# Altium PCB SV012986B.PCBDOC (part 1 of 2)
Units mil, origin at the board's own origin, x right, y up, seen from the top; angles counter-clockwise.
Board outline 2107 x 1920 mil, 4 copper layers (Top Layer, Mid-Layer 1, Mid-Layer 2, Bottom Layer), stack 59.6 mil thick; 51 components, 50 nets, 187 pads, 58 vias.
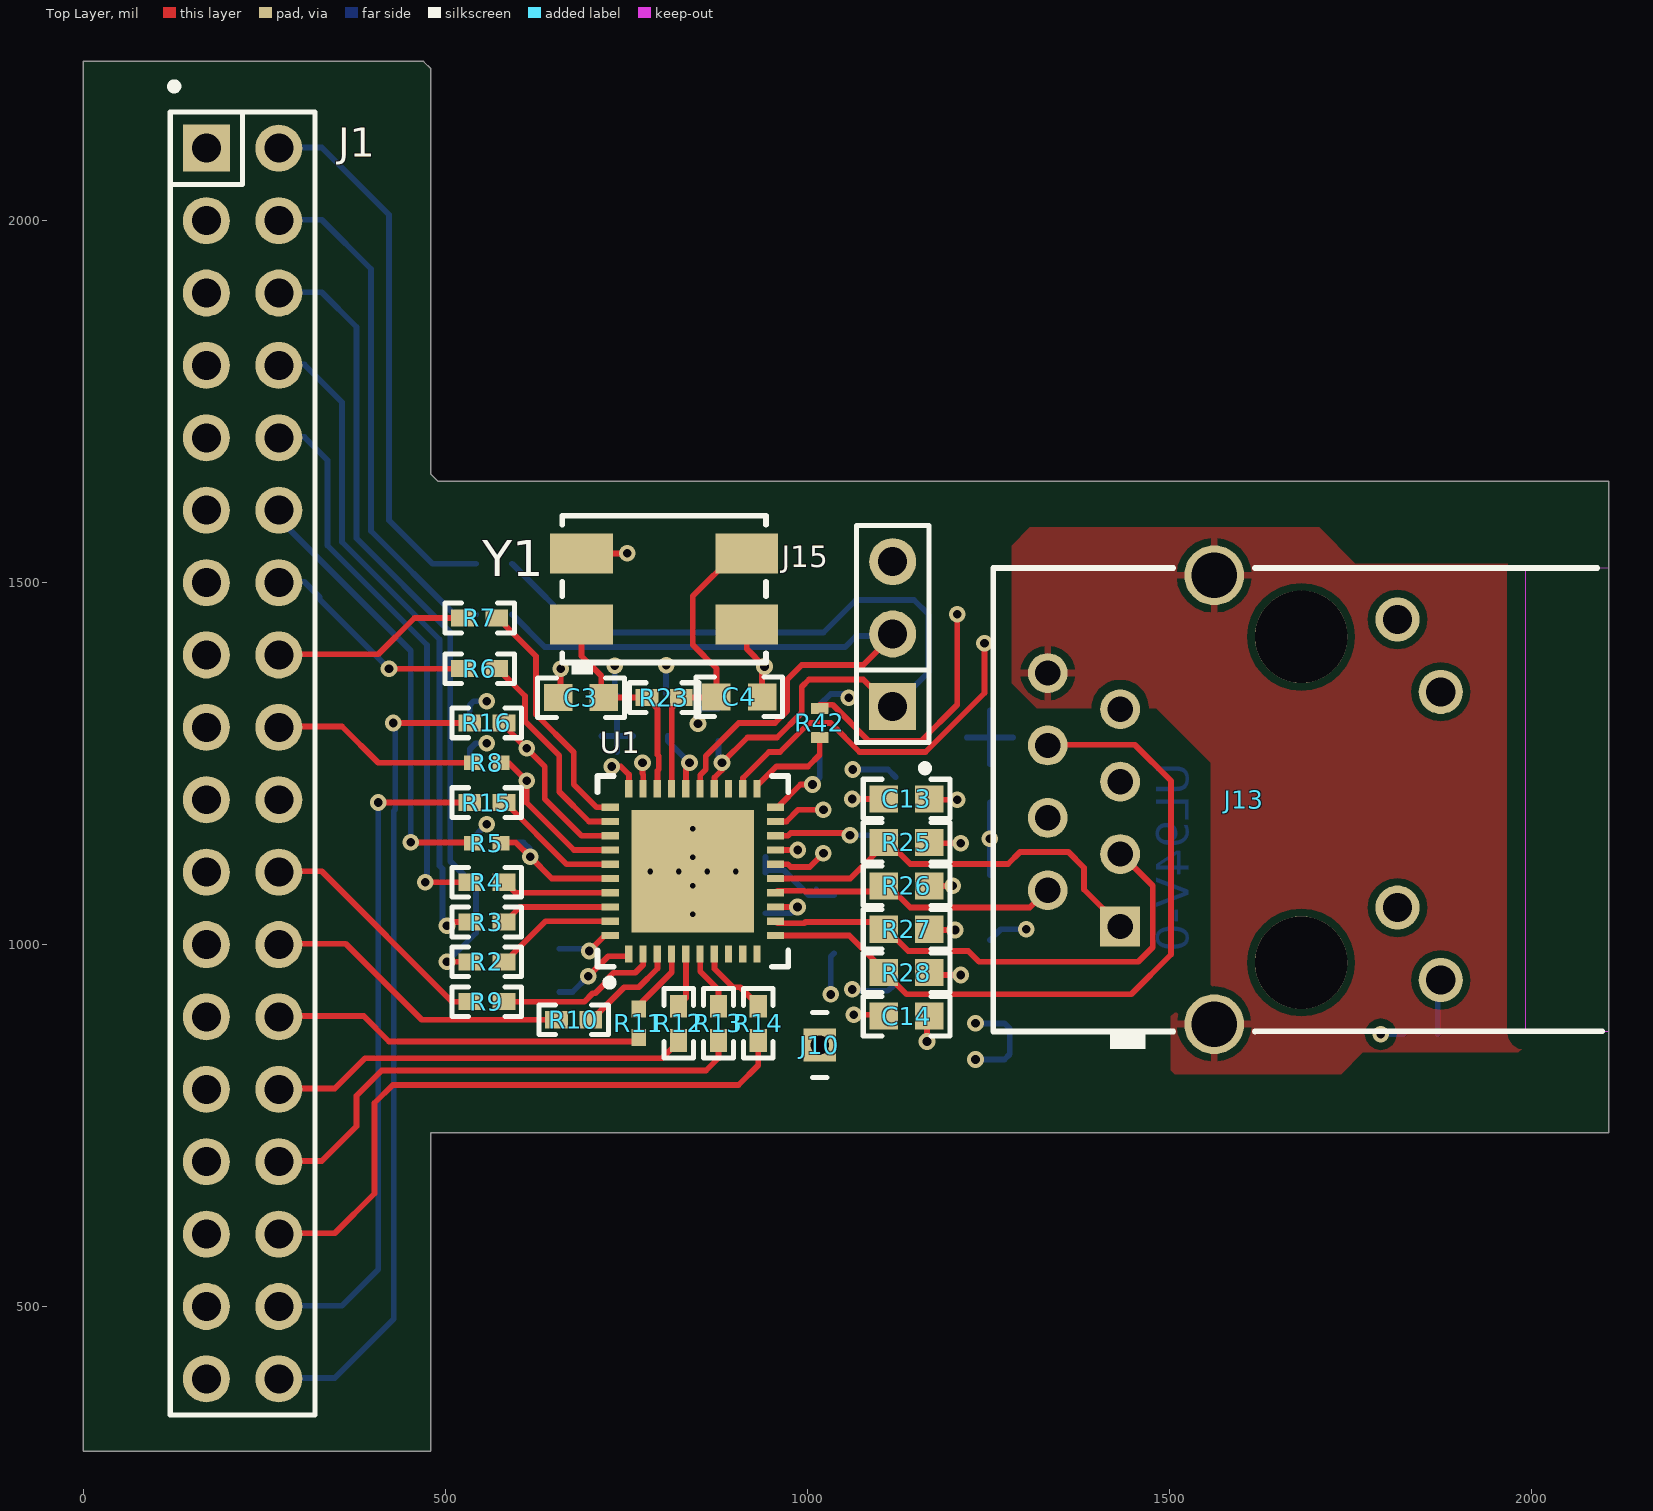
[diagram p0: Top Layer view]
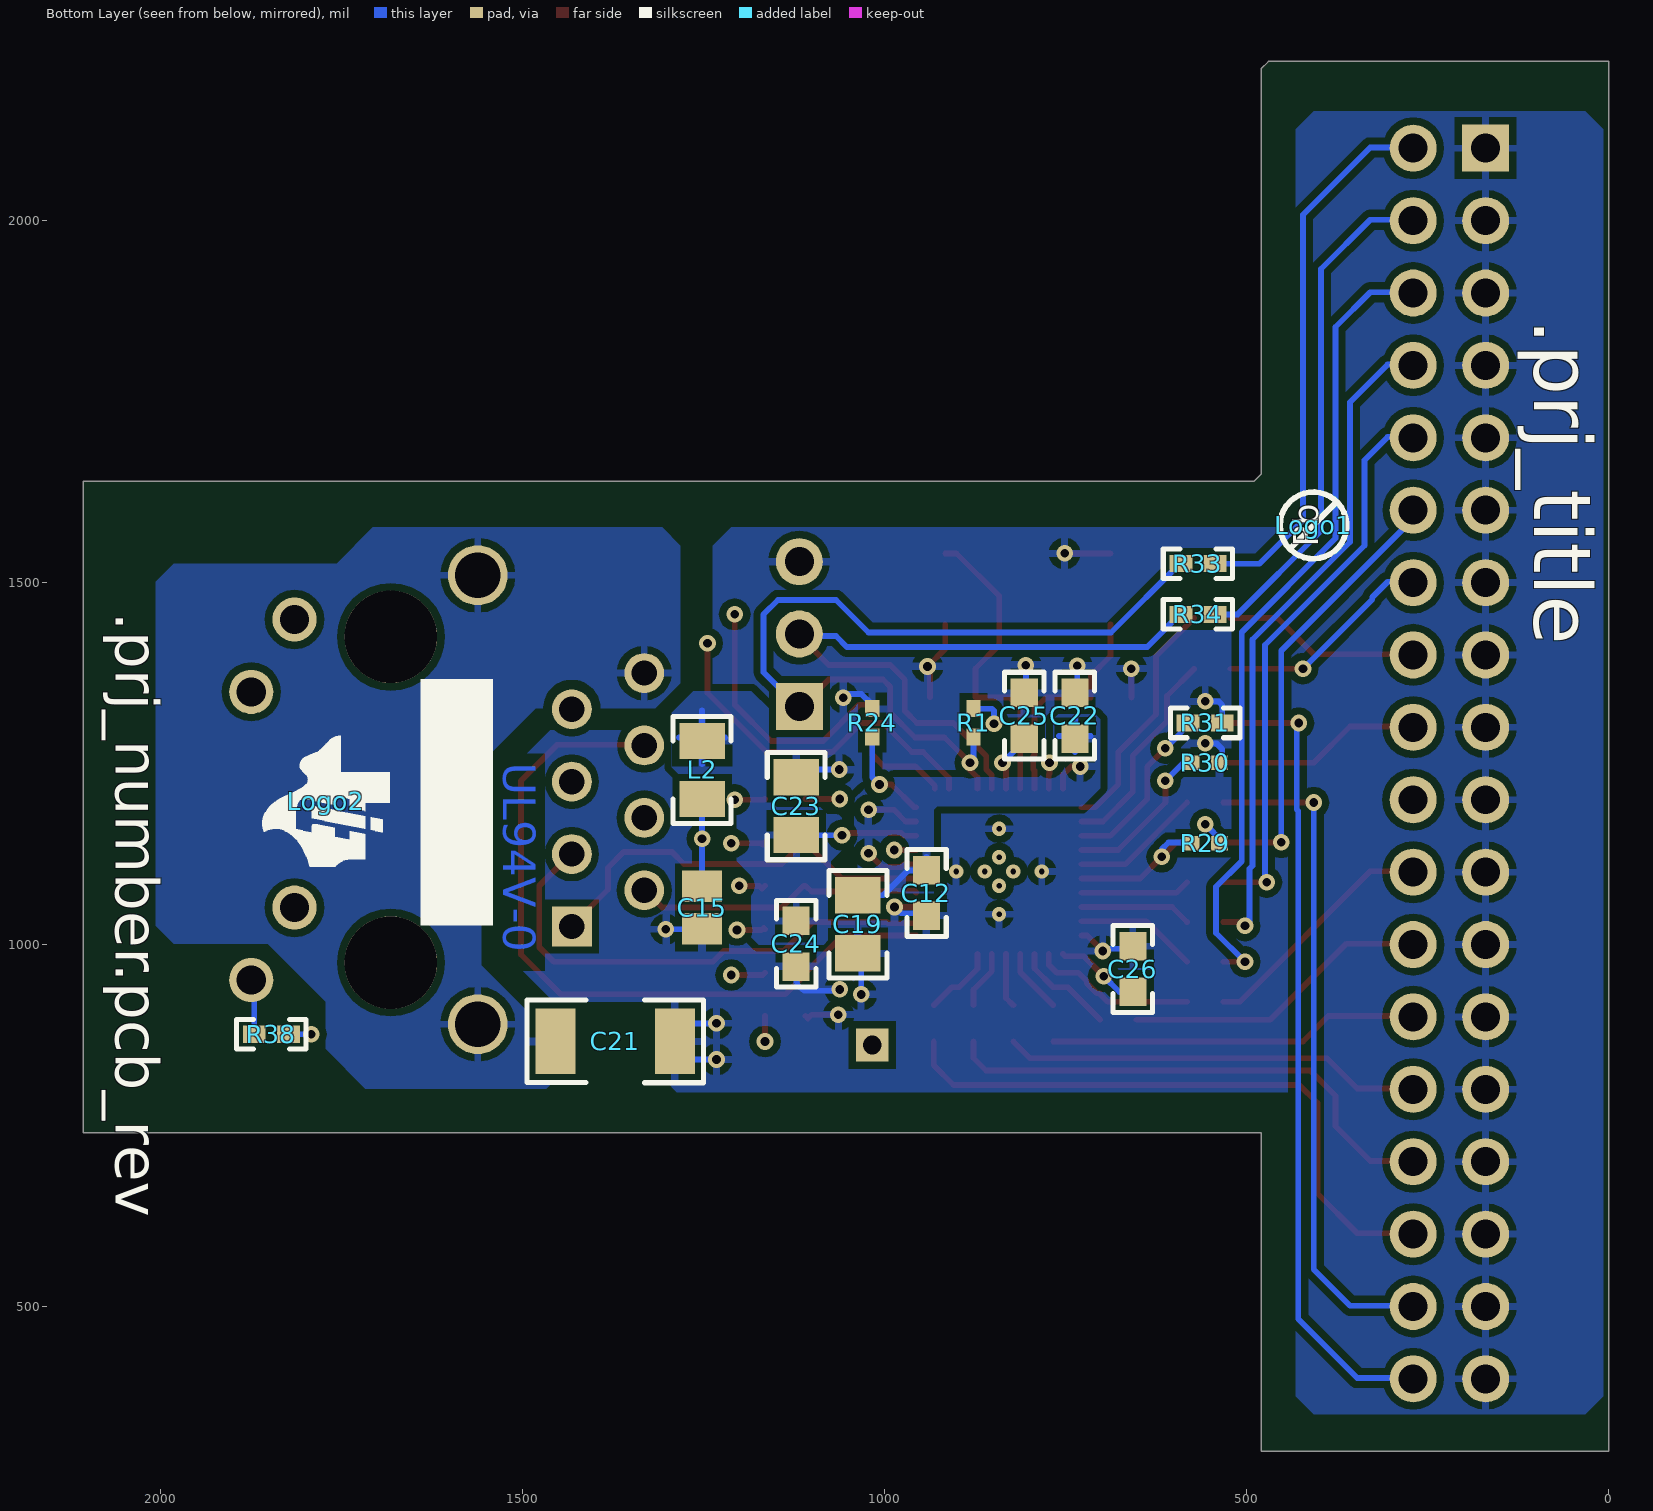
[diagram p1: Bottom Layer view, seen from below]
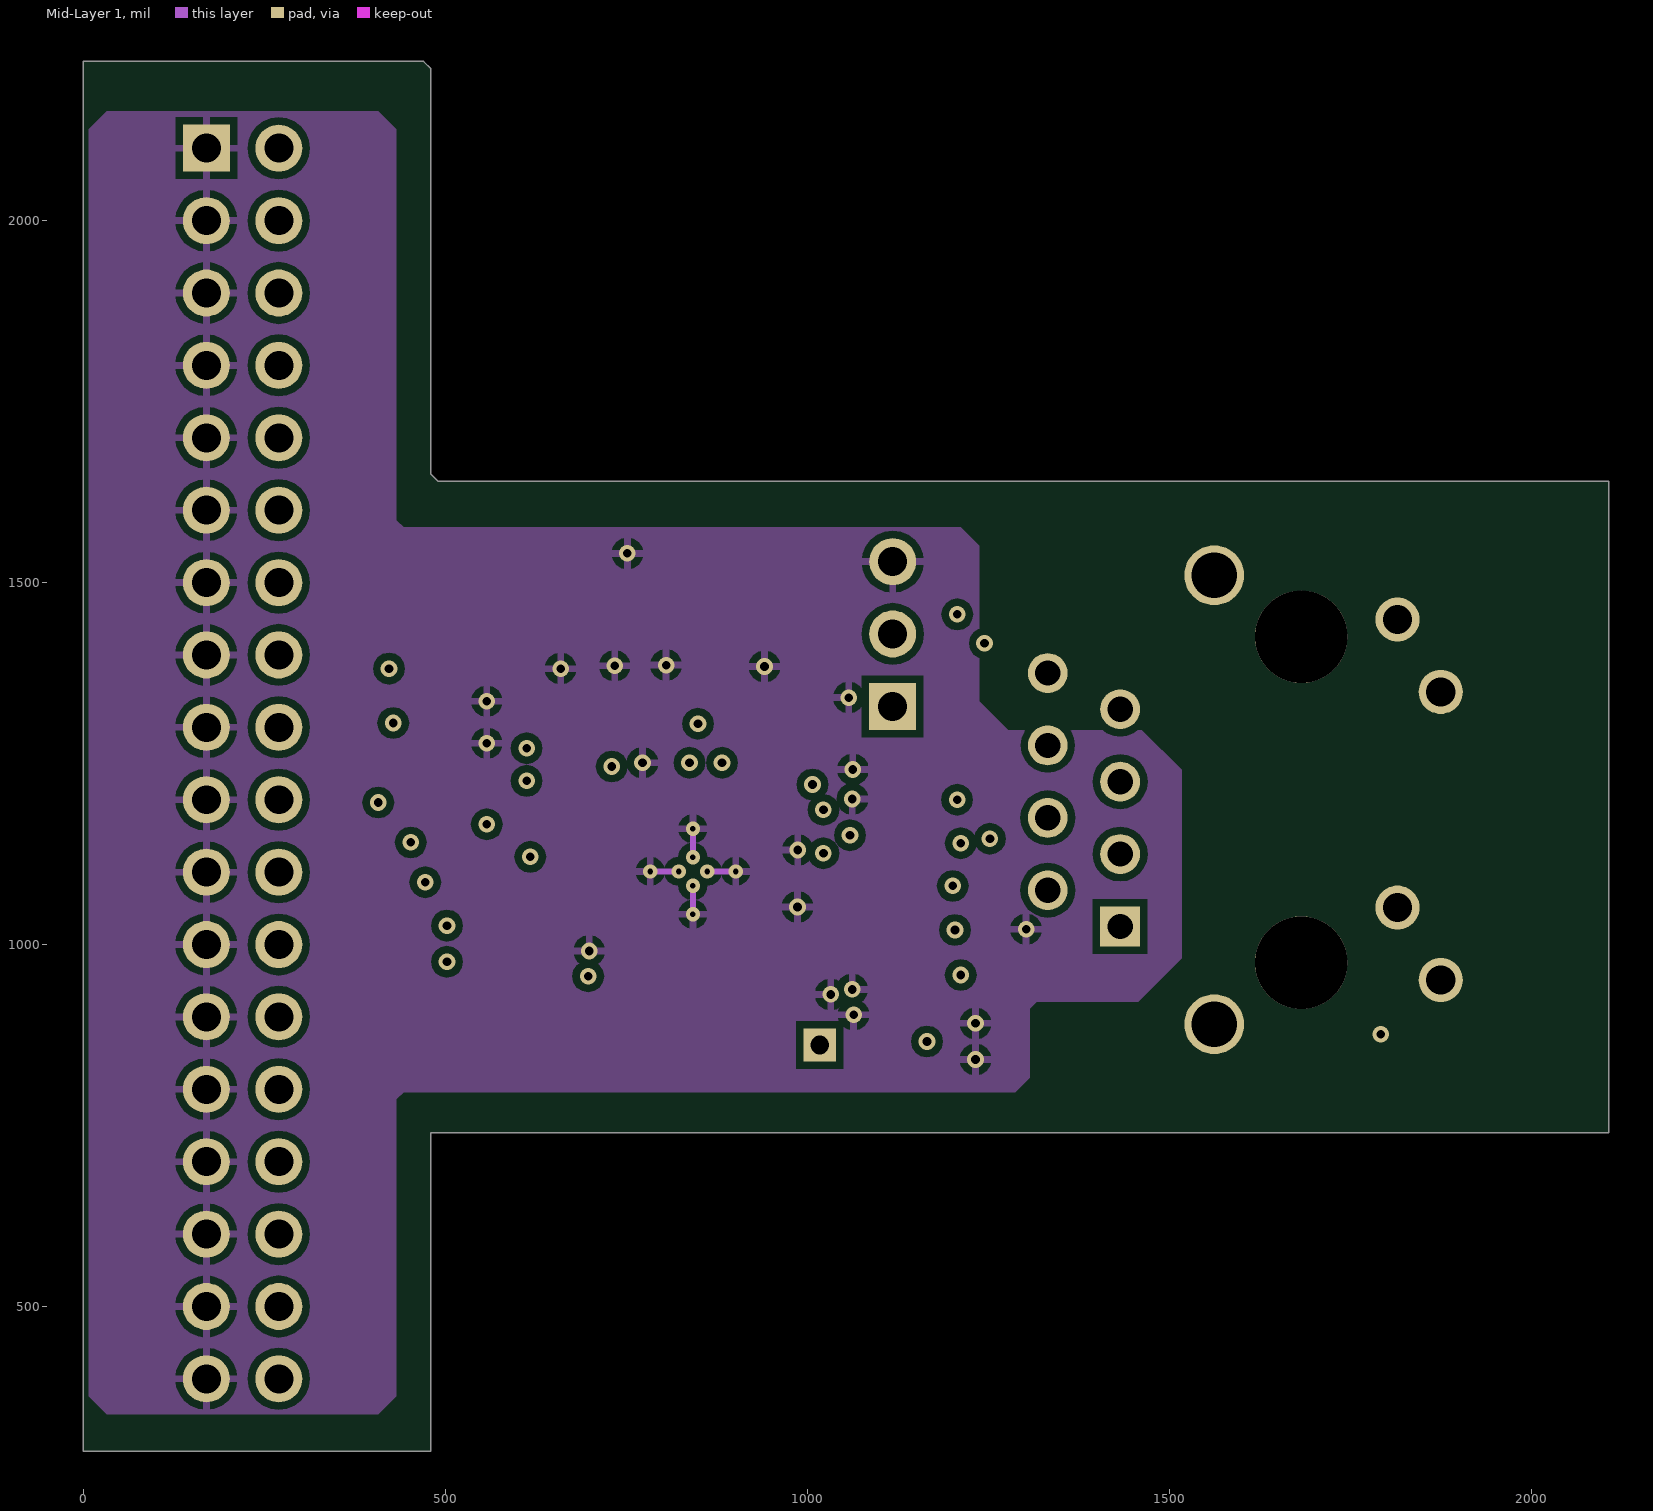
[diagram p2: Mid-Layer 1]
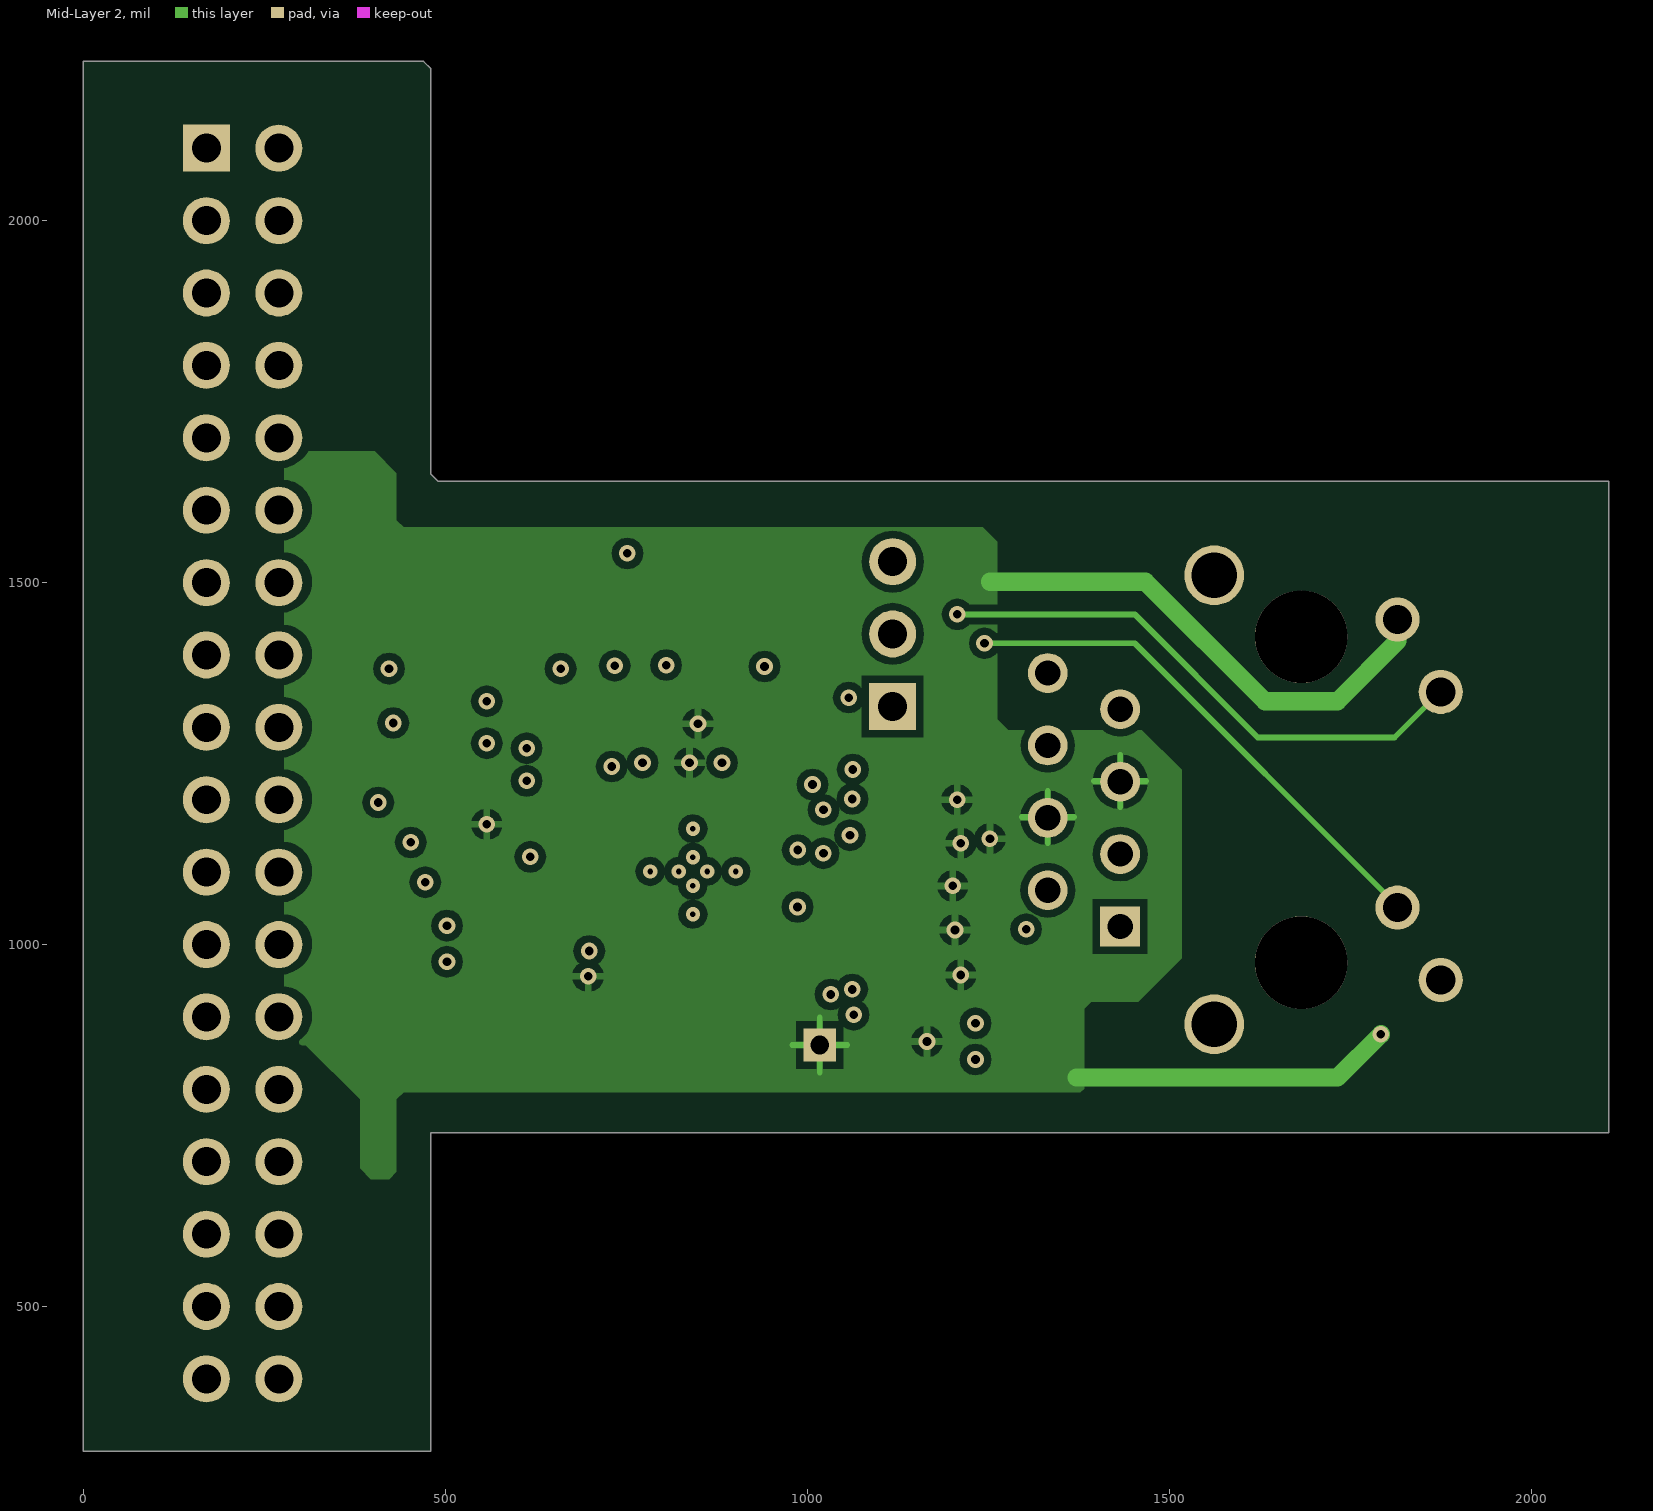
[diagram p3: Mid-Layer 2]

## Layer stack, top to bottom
Top Solder: solder mask 0.4, Solder Resist, Dk 3.5
Top Layer: signal copper 1.4
Dielectric1: core 4, FR-4, Dk 4.8
Mid-Layer 1: signal copper 1.4
Dielectric3: dielectric 46, FR-4, Dk 4.8
Mid-Layer 2: signal copper 1.4
Dielectric2: dielectric 4, FR-4, Dk 4.8
Bottom Layer: signal copper 1.4
Bottom Solder: solder mask 0.4, Solder Resist, Dk 3.5

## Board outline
0,300 0,2220 470,2220 480,2210 480,1650 490,1640 2107,1640 2107,740 480,740 480,300

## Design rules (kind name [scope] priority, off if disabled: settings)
AcuteAngle [All] p1: minimum=4.50000000000000E+0001 checktracksonly=FALSE
AssemblyTestPointUsage [All] p1: valid=2
Clearance Clearance_Keepouts [((IsTrack Or IsArc) And Not InPoly) And IsFree and IsKeepOut vs ((IsTrack Or IsArc) And Not InPoly) And IsFree and IsKeepOut] p1: gap=0
Clearance Clearance_BoardEdge_MountingHoles [OnCopper and InComponentClass('Mounting Holes') vs IsKeepOut] p2: gap=40
Clearance Clearance_BoardEdge_Poly [OnCopper and InPoly vs IsKeepOut] p3: gap=25
Clearance Clearance_BoardEdge [OnCopper and Not InComponentClass('Logo') and not InComponentClass('FiducialMark') and not InRegion(1000,500,4000,800) and Not IsKeepout vs IsKeepOut] p4: gap=75
Clearance Clearance_Poly [InPolygon] p5: gap=10
Clearance [All] p6: gap=6
ComponentClearance ComponentClearance_MountingHoles_FiducialMarks [InComponentClass('Mounting Holes') vs InComponentClass('FiducialMark')] p1: gap=50 collisioncheckmode=3 verticalgap=10 showdistances=FALSE
ComponentClearance ComponentClearance_Shunt [InComponentClass('Header') vs InComponentClass('Shunt')] p2: gap=0 collisioncheckmode=3 verticalgap=0 showdistances=FALSE
ComponentClearance ComponentClearance_Logo [InComponentClass('Logo')] p3: gap=44 collisioncheckmode=3 verticalgap=10 showdistances=FALSE
ComponentClearance ComponentClearance_ScrewToNut [(HasFootprint('NY PMS 440 0025 PH')) vs (HasFootprint('Keystone_1902C'))] p4: gap=5 collisioncheckmode=3 verticalgap=10 showdistances=FALSE
ComponentClearance ComponentClearance_MountingHoles [InComponentClass('Mounting Holes')] p5: gap=250 collisioncheckmode=3 verticalgap=100000 showdistances=FALSE
ComponentClearance ComponentClearance_SmallPassives [HasFootprint('0201*') or HasFootprint('0402*') or HasFootprint('0508') or HasFootprint('0603*') or HasFootprint('0612') or HasFootprint('0805*') or HasFootprint('0815*') or HasFootprint('0830*') or HasFootprint('1206*') or HasFootprint('1210*') or HasFootprint('1808*') or HasFootprint('1812*') or HasFootprint('1825*') or HasFootprint('2010*') or HasFootprint('2220*') or HasFootprint('2225*') or HasFootprint('2512*') or HasFootprint('2728*') or HasFootprint('3518*') vs HasFootprint('0201*') or HasFootprint('0402*') or HasFootprint('0508') or HasFootprint('0603*') or HasFootprint('0612') or HasFootprint('0805*') or HasFootprint('0815*') or HasFootprint('0830*') or HasFootprint('1206*') or HasFootprint('1210*') or HasFootprint('1808*') or HasFootprint('1812*') or HasFootprint('1825*') or HasFootprint('2010*') or HasFootprint('2220*') or HasFootprint('2225*') or HasFootprint('2512*') or HasFootprint('2728*') or HasFootprint('3518*')] p6: gap=20 collisioncheckmode=3 verticalgap=10 showdistances=FALSE
ComponentClearance ComponentClearance_THtoSMT [IsThruComponent vs IsSMTComponent] p7: gap=28 collisioncheckmode=3 verticalgap=30 showdistances=FALSE
ComponentClearance ComponentClearance_THtoTH [IsThruComponent vs IsThruComponent] p8: gap=80 collisioncheckmode=3 verticalgap=30 showdistances=FALSE
ComponentClearance [All] p9: gap=29 collisioncheckmode=3 verticalgap=40 showdistances=FALSE
DiffPairsRouting [All] p1: maxlimit=100 minlimit=10 mostfreqgap=10 toplayer_minwidth=15 toplayer_maxwidth=15 toplayer_prefwidth=15 midlayer1_minwidth=15 midlayer1_maxwidth=15 midlayer1_prefwidth=15 midlayer2_minwidth=15 midlayer2_maxwidth=15 midlayer2_prefwidth=15 bottomlayer_minwidth=15 bottomlayer_maxwidth=15 bottomlayer_prefwidth=15 maxuncoupledlength=1000
FabricationTestPointUsage TestPointUsage [All] p1: valid=2 allowmultiple=FALSE
FabricationTestpoint Testpoint [All] p1: side=3 testpointundercomponent=TRUE minsize=40 maxsize=100 preferedsize=60 minholesize=0 maxholesize=40 preferedholesize=32 testpointgrid=1 allowsidetop=TRUE allowsidebottom=TRUE usegrid=TRUE gridtolerance=0.01
FanoutControl Fanout_LCC [IsLCC] p1: bgadir=Out bgaviamode=Centered fanoutstyle=Auto fanoutdirection=Alternating viagrid=1 // Fanout_LCC (Default Rule)
FanoutControl Fanout_BGA [IsBGA] p2: bgadir=Out bgaviamode=Centered fanoutstyle=Auto fanoutdirection=Alternating viagrid=1 // Fanout_BGA (Default Rule)
FanoutControl Fanout_Default [All] p4: bgadir=Out bgaviamode=Centered fanoutstyle=Auto fanoutdirection=Alternating viagrid=1 // Fanout_Default (Default Rule)
FanoutControl Fanout_Small [(CompPinCount < 5)] p5: bgadir=Out bgaviamode=Centered fanoutstyle=Auto fanoutdirection=OutThenIn viagrid=1 // Fanout_Small (Default Rule)
HoleSize [All] p1: absolutevalues=TRUE maxlimit=251 minlimit=7 maxpercent=80.000 minpercent=20.000
MinimumAnnularRing MinimumAnnularRing_ThermalPadVias [IsVia and InAnyComponent] p1: minimumring=5.91
MinimumAnnularRing [All] p2: minimumring=5
MinimumSolderMaskSliver MinimumSolderMaskSliver_Logo [InComponentClass('Logo') vs InComponentClass('Logo')] p1: minsoldermaskwidth=0.7
MinimumSolderMaskSliver [All] p2: minsoldermaskwidth=0.08
PlaneConnect [All] p1: planeconnectstyle=Relief reliefexpansion=10 reliefentries=4 reliefconductorwidth=10 reliefairgap=10
PolygonConnect [All] p1: connectstyle=Relief reliefconductorwidth=10 reliefentries=4 polygonreliefangle="90 Angle" airgapwidth=10
RoutingVias ThermalPadVias [IsVia and InAnyComponent] p1: holewidth=7.87 width=19.68 viastyle="Through Hole" minholewidth=7.87 minwidth=19.68 maxholewidth=12.99 maxwidth=23.62
RoutingVias [All] p2: holewidth=16 width=34 viastyle="Through Hole" minholewidth=7.87 minwidth=20 maxholewidth=40 maxwidth=65
SilkToBoardRegionClearance [Not ((IsComment or IsDesignator) And (Hide <> 'False')) and not InRegion(1000,500,4000,800)] p1:
SilkToSilkClearance SilkToSilkClearance_Pb-FreeLogo [(HasFootprint('Pb-Free_Overlay_Medium') OR HasFootprint('Pb-Free_Overlay_Small')) vs (HasFootprint('Pb-Free_Overlay_Medium') OR HasFootprint('Pb-Free_Overlay_Small'))] p1: silktosilkclearance=0
SilkToSilkClearance [All] p2: silktosilkclearance=5
SilkToSolderMaskClearance "Silk to Solder Mask Opening" [All] p1: minsilkscreentomaskgap=0 clearancetoexposedcopper=FALSE
SolderMaskExpansion [All] p1: expansion=1.97
UnpouredPolygon [All] p1: allowunpoured=FALSE
Width [All] p1: maxlimit=100 minlimit=6 preferedwidth=10 checkconnectedcopper=TRUE
14 further rules are at their usual default settings.

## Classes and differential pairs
component class Header: J1 J15
component class Logo: Logo2

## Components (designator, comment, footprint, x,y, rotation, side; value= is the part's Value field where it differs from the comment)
C3 "GRM1885C1H180JA01D" 0603 687.3,1341.1 r180 top
C4 "GRM1885C1H180JA01D" 0603 906,1342 r0 top
C12 "GRM188R61C104KA01D" 0603 942.3,1071.1 r270 bottom
C13 "GRM188R61C104KA01D" 0603 1137.3,1201.1 r180 top
C14 "GRM188R61C104KA01D" 0603 1137.3,901.1 r180 top
C15 "C0805C106M8PACTU" 0805L 1252.3,1051.1 r90 bottom
C19 "C0805C106M8PACTU" 0805_HV 1037,1028 r90 bottom
C21 "GR442QR73D152KW01L" 1808 1372.3,866.1 r180 bottom
C22 "GRM188R61C104KA01D" 0603 737.3,1316.1 r90 bottom
C23 "GRM216R61A105KA01D" 0805_HV 1122.3,1191.1 r270 bottom
C24 "GRM188R61C104KA01D" 0603 1122.3,1001.1 r90 bottom
C25 "GRM188R61C104KA01D" 0603 807.3,1316.1 r90 bottom
C26 "GRM188R61C104KA01D" 0603 657.3,966.1 r270 bottom
J1 "TSW-118-07-G-D" TSW-118-07-G-D 220,1250 r270 top
J10 "TMS-101-02-T-S" SAMTEC_TMS-101-02-T-S 1017.3,861.1 r0 top
J13 "J0011D21BNL" Pulse_J0011D21BNL 2107,1200 r90 top
J15 "TSW-103-07-G-S" TSW-103-07-G-S 1118,1429 r90 top
L2 "BLM21AG121SN1D" 0805_HV 1252.3,1241.1 r270 bottom
Logo1 "Pb-Free Symbol" Pb-Free_Overlay_Small 408,1579 r90 bottom
Logo2 "Texas Instruments" TI_Symbol_Overlay_Small 1772,1198 r270 bottom
R1 "CRCW04021K50FKED" 0402L 877.3,1306.1 r90 bottom
R2 "CRCW040247R0JNED" 0402 557.3,976.1 r0 top
R3 "CRCW040247R0JNED" 0402 557.3,1031.1 r0 top
R4 "CRCW040247R0JNED" 0402 557.3,1086.1 r0 top
R5 "CRCW040247R0JNED" 0402L 557,1140 r0 top
R6 "CRCW040247R0JNED" 0402 547.3,1381.1 r0 top
R7 "CRCW040247R0JNED" 0402 547.3,1451.1 r0 top
R8 "CRCW040247R0JNED" 0402L 557.3,1251.1 r0 top
R9 "CRCW040247R0JNED" 0402 557.3,921.1 r0 top
R10 "CRCW040233R0JNED" 0402 677.3,896.1 r0 top
R11 "CRCW040233R0JNED" 0402L 767.3,891.1 r90 top
R12 "CRCW040233R0JNED" 0402 822.3,891.1 r90 top
R13 "CRCW040233R0JNED" 0402 877.3,891.1 r90 top
R14 "CRCW040233R0JNED" 0402 932.3,891.1 r90 top
R15 "CRCW040247R0JNED" 0402 557.3,1196.1 r0 top
R16 "CRCW040247R0JNED" 0402 557.3,1306.1 r0 top
R23 "CRCW04021M00JNED" 0402 802.3,1341.1 r180 top
R24 "CRCW04024K87FKED" 0402L 1017.3,1306.1 r90 bottom
R25 "CRCW060349R9FKEA" 0603 1137.3,1141.1 r0 top
R26 "CRCW060349R9FKEA" 0603 1137.3,1081.1 r0 top
R27 "CRCW060349R9FKEA" 0603 1137.3,1021.1 r0 top
R28 "CRCW060349R9FKEA" 0603 1137.3,961.1 r0 top
R29 "CRCW04022K20JNED" 0402L 557,1140 r180 bottom
R30 "CRCW04022K20JNED" 0402L 557.3,1251.1 r0 bottom
R31 "CRCW04022K20JNED" 0402 557.3,1306.1 r180 bottom
R33 "CRCW04020000Z0ED" 0402 567.3,1526.1 r0 bottom
R34 "CRCW04020000Z0ED" 0402 567.3,1456.1 r0 bottom
R38 "CRCW0402274RFKED" 0402 1847.3,876.1 r180 bottom
R42 "CRCW0402274RFKED" 0402S 1017.3,1306.1 r90 top
U1 "DP83848J/K" SQA40B 842,1101 r90 top
Y1 "EA5070PA18-25.000M" Ecliptek_EA5070 802.3,1491.1 r90 top

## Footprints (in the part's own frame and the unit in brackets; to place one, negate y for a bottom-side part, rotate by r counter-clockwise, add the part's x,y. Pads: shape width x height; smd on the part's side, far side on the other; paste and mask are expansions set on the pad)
0402 [mm] "0402 from SM-752 data"
  rect 0.8x0.6 smd: 1(-0.6,0) 2(0.6,0)
  silkscreen extent -1.22,-0.52 1.22,0.52, body extent -0.55,-0.3 0.55,0.3, height 0.6
0402L [mm] "0402 from SM-752 data"
  rect 0.6x0.5 smd: 1(-0.5,0) 2(0.5,0)
  body extent -0.55,-0.3 0.55,0.3, height 0.6
0402S [mil] "Based on C0402S footprint from PADS legacy"
  rect 15x24 smd: 1(-20,0) 2(20,0)
  body extent -22,-12 22,12, height 24
0603 [mm] "0603 from SM-752 data"
  rect 1x0.95 smd: 1(-0.8,0) 2(0.8,0)
  silkscreen extent -1.52,-0.69 1.52,0.69, body extent -0.87,-0.47 0.87,0.47, height 0.85
0805_HV [mil] "0805 with 30mil clearance between pads"
  rect 50x63 smd: 1(-40,0) 2(40,0)
  silkscreen extent -74,-40 74,40, body extent -43,-29 43,29, height 43
0805L [mm] "0805 from SM-752 data"
  rect 1.1x1.4 smd: 1(-0.75,0) 2(0.75,0)
  body extent -1.1,-0.72 1.1,0.72, height 1.1
1808 [mm] "Chip Capacitor, Body 4.6x2.0mm, IPC Medium Density"
  rect 1.4x2.3 smd: 1(-2.1,0) 2(2.1,0)
  silkscreen extent -3.1,-1.45 3.1,1.45, body extent -2.47,-1.2 2.47,1.2, height 2.03
Ecliptek_EA5070 [mm] "SMD, 4-Leads, Body 7x5mm"
  rect 1.4x2.2 smd: 1(-1.25,2.9) 2(-1.25,-2.9) 3(1.25,-2.9) 4(1.25,2.9)
  silkscreen extent -3,-3.57 2.58,3.57, body extent -2.58,-3.58 2.58,3.58, height 1.31
Pb-Free_Overlay_Small [mil]
  silkscreen extent -46,-46 46,46
Pulse_J0011D21BNL [mm] "Connector, RJ-45 with integrated magnetics, 1x1, R/A, TH"
  rect 1.4x1.4 hole 0.89: 1(-4.445,17.14)
  round 1.4 hole 0.89: 2(-3.175,19.68) 3(-1.905,17.14) 4(-0.635,19.68) 5(0.635,17.14) 6(1.905,19.68) 7(3.175,17.14) 8(4.445,19.68)
  round 1.55 hole 1.02: 9(-6.325,5.89) 10(-3.785,7.41) 11(3.785,5.89) 12(6.325,7.41)
  round 2.1 hole 1.6: 13(-7.875,13.84) 14(7.875,13.84)
  round 3.25 hole 3.25 unplated mask+0: MH1(-5.715,10.79) MH2(5.715,10.79)
  Top Layer keep-out region: -8.13,0 8.13,0 8.13,2.92 -8.13,2.92
  silkscreen extent -8.75,0.23 8.13,21.59, body extent -8.13,0 8.13,21.59, height 13.84
SAMTEC_TMS-101-02-T-S [mm] "SAMTEC"
  rect 1.15x1.15 hole 0.66: 1(0,0)
  silkscreen extent -0.25,-1.14 0.25,1.14, body extent -0.63,-1.14 0.63,1.14, height 5.08
SQA40B [mm] "QFN, 40-Leads, Body 6x6mm, Pitch 0.5mm, NSC Recommended"
  rect 0.6x0.25 smd paste-0.125 mask+0.051: 1(-2.9,2.25) 2(-2.9,1.75) 3(-2.9,1.25) 4(-2.9,0.75) 5(-2.9,0.25) 6(-2.9,-0.25) 7(-2.9,-0.75) 8(-2.9,-1.25) 9(-2.9,-1.75) 10(-2.9,-2.25) 21(2.9,-2.25) 22(2.9,-1.75) 23(2.9,-1.25) 24(2.9,-0.75) 25(2.9,-0.25) 26(2.9,0.25) 27(2.9,0.75) 28(2.9,1.25) 29(2.9,1.75) 30(2.9,2.25)
  rect 0.25x0.6 smd paste-0.125 mask+0.051: 11(-2.25,-2.9) 12(-1.75,-2.9) 13(-1.25,-2.9) 14(-0.75,-2.9) 15(-0.25,-2.9) 16(0.25,-2.9) 17(0.75,-2.9) 18(1.25,-2.9) 19(1.75,-2.9) 20(2.25,-2.9) 31(2.25,2.9) 32(1.75,2.9) 33(1.25,2.9) 34(0.75,2.9) 35(0.25,2.9) 36(-0.25,2.9) 37(-0.75,2.9) 38(-1.25,2.9) 39(-1.75,2.9) 40(-2.25,2.9)
  rect 4.3x4.3 smd paste-2.15 mask+0.051: 41(0,0)
  silkscreen extent -4.02,-3.35 3.35,3.35, body extent -3.05,-3.05 3.05,3.05, height 0.8
TI_Symbol_Overlay_Small [mil]
  silkscreen extent -90,-88 91,88
TSW-103-07-G-S [mm] "Samtec 100mil, 1x3, 230 mil above insulator"
  rect 1.65x1.65 hole 1.016: 1(-2.54,0)
  round 1.65 hole 1.016: 2(0,0) 3(2.54,0)
  silkscreen extent -4.83,-1.27 3.81,1.27, body extent -3.81,-1.27 3.81,1.27, height 8.38
TSW-118-07-G-D [mm] "Samtec 100mil, 2x18, 230 mil above insulator"
  rect 1.65x1.65 hole 1.016 mask+0: 1(-21.59,-1.27)
  round 1.65 hole 1.016 mask+0: 2(-21.59,1.27) 3(-19.05,-1.27) 4(-19.05,1.27) 5(-16.51,-1.27) 6(-16.51,1.27) 7(-13.97,-1.27) 8(-13.97,1.27) 9(-11.43,-1.27) 10(-11.43,1.27) 11(-8.89,-1.27) 12(-8.89,1.27) 13(-6.35,-1.27) 14(-6.35,1.27) 15(-3.81,-1.27) 16(-3.81,1.27) 17(-1.27,-1.27) 18(-1.27,1.27) 19(1.27,-1.27) 20(1.27,1.27) 21(3.81,-1.27) 22(3.81,1.27) 23(6.35,-1.27) 24(6.35,1.27) 25(8.89,-1.27) 26(8.89,1.27) 27(11.43,-1.27) 28(11.43,1.27) 29(13.97,-1.27) 30(13.97,1.27) 31(16.51,-1.27) 32(16.51,1.27) 33(19.05,-1.27) 34(19.05,1.27) 35(21.59,-1.27) 36(21.59,1.27)
  silkscreen extent -23.88,-2.54 22.86,2.54, body extent -22.86,-2.54 22.86,2.54, height 8.38

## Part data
C3 C4: "CAP, CERM, 18 pF, 50 V, +/- 5%, C0G/NP0, 0603"
C12 C13 C14 C22 C24 C25 C26: "CAP, CERM, 0.1 µF, 16 V, +/- 10%, X5R, 0603"
C15 C19: "CAP, CERM, 10 µF, 10 V, +/- 20%, X5R, 0805"
C21: "CAP, CERM, 1500 pF, 2000 V, +/- 10%, X7R, 1808"
C23: "CAP, CERM, 1 µF, 10 V, +/- 10%, X5R, 0805"
J1: "Header, 100mil, 18x2, Gold, TH"
J10: "Header, 1x1, Tin, TH"
J13: "Connector, RJ-45 with integrated magnetics, 1x1, Gold, R/A, TH"
J15: "Header, 100mil, 3x1, Gold, TH"
L2: "Ferrite Bead, 120 ohm @ 100 MHz, 0.8 A, 0805"
Logo1: library part Pb-Free
Logo2: library part TI_Logo, "Texas Instrument Corporate Signature"
R1: "RES, 1.50 k, 1%, 0.063 W, 0402"
R2 R3 R4 R5 R6 R7 R8 R9 R15 R16: "RES, 47, 5%, 0.063 W, 0402"
R10 R11 R12 R13 R14: "RES, 33, 5%, 0.063 W, 0402"
R23: "RES, 1.0 M, 5%, 0.063 W, 0402"
R24: "RES, 4.87 k, 1%, 0.063 W, 0402"
R25 R26 R27 R28: "RES, 49.9, 1%, 0.1 W, 0603"
R29 R30 R31: "RES, 2.2 k, 5%, 0.063 W, 0402"
R33 R34: "RES, 0, 5%, 0.063 W, 0402"
R38 R42: "RES, 274, 1%, 0.063 W, 0402"
U1: library part DP83848JSQ, "PHYTER® Mini LS Commercial Temperature Single Port 10/100 Mb/s Ethernet Transceiver, 40-pin LLP"
Y1: "Quartz Crystal Resonator, 25 MHz, SMD"

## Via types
v1: diameter 23, hole 12, Top Layer to Bottom Layer, 50 vias
v2: diameter 19.68, hole 7.87, Top Layer to Bottom Layer, 8 vias

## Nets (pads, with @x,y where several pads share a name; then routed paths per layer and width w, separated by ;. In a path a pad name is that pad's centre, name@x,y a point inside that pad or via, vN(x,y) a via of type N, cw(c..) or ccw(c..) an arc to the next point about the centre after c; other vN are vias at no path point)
3V3: C13.1 C14.1 C15.2 C25.1 C26.2 J10.1 J13.4 J13.5 J13.12 L2.2 R1.2 R25.2 R26.2 R27.2 R28.2 R29.2 R38.2 U1.1 U1.26 | length 2258.7
  Top Layer w8: v1(697.3,956.1) 724.94,983.74 750.53,983.74 U1.1@753.72,986.93 ; U1.26@832.46,1215.27 832.46,1246.26 v1(837.3,1251.1) ; v1(1165.3,866.1) C14.1@1165.3,901.1 ; R28.2@1165.3,961.1 1168.4,958 v1(1212,958) ; R27.2@1165.3,1021.1 1167.2,1023 1170.2,1020 v1(1204,1020) ; R26.2@1165.3,1081.1 1169.4,1077 1173.4,1081 v1(1201,1081) ; R25.2@1165.3,1141.1 1168.4,1138 1170.4,1140 v1(1212,1140) ; C13.1@1165.3,1201.1 1166.4,1200 v1(1207,1200)
  Mid-Layer 2 w8: 979.28,861.1 J10.1@1017.3,861.1 ; 1017.3,823.08 J10.1@1017.3,861.1 ; 1017.3,899.12 J10.1@1017.3,861.1 ; 1055.32,861.1 J10.1@1017.3,861.1 ; 1296.28,1176.1 J13.4@1332.3,1176.1 ; 1332.3,1140.08 J13.4@1332.3,1176.1 ; 1332.3,1212.12 J13.4@1332.3,1176.1 ; 1368.32,1176.1 J13.4@1332.3,1176.1 ; 1396.28,1226.1 J13.5@1432.3,1226.1 ; 1432.3,1190.08 J13.5@1432.3,1226.1 ; 1432.3,1262.12 J13.5@1432.3,1226.1 ; 1468.32,1226.1 J13.5@1432.3,1226.1
  Mid-Layer 2 w25: 1252.3,1501.1 1467.3,1501.1 1632.3,1336.1 1732.3,1336.1 1815.3,1419.1 J13.12@1815.3,1450.1 ; 1372.3,816.1 1732.3,816.1 v1(1792.3,876.1)
  Bottom Layer w8: R29.2@532.3,1141.1 R29.2@533.68,1142.48 ; R29.2@533.68,1141.1 R29.2@533.68,1142.48 ; v1(557.3,1166.1) R29.2@533.68,1142.48 ; C26.2@657.3,934.6 675.8,934.6 v1(697.3,956.1) ; C25.1@807.3,1288.1 807.3,1281.1 v1(837.3,1251.1) ; v1@851.2,1305 v1(849,1305) 849,1323 851.79,1325.79 R1.2@877.3,1325.79 ; C15.2@1252.3,1096.1 v1(1252.3,1146.1) L2.2@1252.3,1196.1 ; v1(1792.3,876.1) R38.2@1823.68,876.1
AVDD33: C23.2 C24.2 L2.1 U1.18 | length 306.7
  Top Layer w8: U1.18@956.47,1150.31 973.28,1150.31 977.1,1154.13 1055.87,1154.13 v1(1058.93,1151.07)
  Bottom Layer w8: v1(1058.93,1151.07) C23.2@1122.3,1151.1 ; 1220.28,1286.1 L2.1@1252.3,1286.1 ; 1252.3,1249.08 L2.1@1252.3,1286.1 ; 1252.3,1323.12 L2.1@1252.3,1286.1 ; 1284.32,1286.1 L2.1@1252.3,1286.1
COL: R15.2 U1.35 | length 181.1
  Top Layer w8: R15.2@582.3,1196.1 667.46,1110.94 U1.35@728.13,1110.94
CRS: R16.2 R31.1 U1.33 | length 287.1
  Top Layer w8: R16.2@582.3,1306.1 582.3,1301.1 v1(612.3,1271.1) 637.3,1246.1 637.3,1201.1 688.09,1150.31 U1.33@728.13,1150.31
  Bottom Layer w8: R31.1@582.3,1306.1 582.3,1301.1 v1(612.3,1271.1)
GND: C3.2 C4.2 C12.2 C13.2 C14.2 C15.1 C19.1 C21.2 C22.2 C23.1 C24.1 C25.2 C26.1 J1.1 J1.3 J1.5 J1.7 J1.9 J1.11 J1.13 J1.15 J1.17 J1.19 J1.21 J1.23 J1.25 J1.27 J1.29 J1.31 J1.33 J1.35 J15.3 R24.2 R30.1 R31.2 U1.13 U1.17 U1.29 U1.40 U1.41 Y1.2 Y1.4 | length 1310.1
  Top Layer w8: C3.2@659.3,1341.1 v1(659.3,1381.1) ; Y1.4@688.13,1540.31 v1(751.51,1540.31) ; v1(698.72,991.1) 720.14,1012.52 U1.40@728.13,1012.52 ; v1(772.3,1251.1) 772.3,1236.1 773.4,1235 U1.29@773.4,1215.27 ; Y1.2@916.47,1441.89 916.47,1408.53 v1(941,1384) ; C4.2@937.5,1342 937.5,1380.5 v1@939.2,1382.2 ; U1.13@956.47,1051.89 v1(986.51,1051.89) ; U1.17@956.47,1130.63 v1(986.83,1130.63) ; v1(1062.3,1201.1) C13.2@1109.3,1201.1 ; v1(1064,903) 1101.2,903 1106.2,898 C14.2@1109.3,901.1
  Mid-Layer 1 w8: v2(782.94,1101) v2(822.32,1101) ; v2(842,1041.94) v2(842,1081.32) ; v2(842,1120.68) v2(842,1160.06) ; v2(861.69,1101) v2(901.06,1101)
  Bottom Layer w8: R30.1@533.68,1251.1 533.68,1269.68 542.1,1278.1 v1(557.3,1278.1) ; R31.2@533.68,1306.1 533.68,1330.68 539.1,1336.1 v1(557.3,1336.1) ; C26.1@657.3,994.1 695.72,994.1 v1(698.72,991.1) ; v1(734,1385) 734,1347.4 C22.2@737.3,1344.1 ; v1(805,1386) 805,1346.4 C25.2@807.3,1344.1 ; C12.2@942.3,1043.1 977.72,1043.1 v1(986.51,1051.89) ; R24.2@1017.3,1331.1 1032.3,1346.1 1052.3,1346.1 v1(1057.3,1341.1) ; v1(1032.3,931.1) 1032.3,983.3 C19.1@1037,988 ; v1(1062,938) 1063.9,936.1 1110.94,936.1 1120.85,943.89 C24.1@1122.3,956.1 ; v1(1062.96,1241.76) 1111.64,1241.76 C23.1@1122.3,1231.1 ; v1(1232.3,841.1) 1272.3,841.1 1279.8,848.6 1279.8,883.6 1272.3,891.1 v1(1232.3,891.1) ; C15.1@1252.3,1006.1 1267.3,1021.1 v1(1302.3,1021.1)
GND_CHASSIS: C21.1 J13.8 J13.13 J13.14
LED_LINK: J13.10 U1.22 | length 1220.5
  Top Layer w8: U1.22@911.2,1215.27 911.2,1230 947.3,1266.1 962.3,1266.1 1002.3,1306.1 1032.3,1306.1 1072.3,1266.1 1163.31,1266.1 1244.8,1347.59 v1(1244.8,1416.1)
  Mid-Layer 2 w8: v1(1244.8,1416.1) 1452.3,1416.1 1815.3,1053.1 J13.10@1815.3,1052.1
LED_SPD: R42.1 U1.21 | length 132.3
  Top Layer w8: U1.21@930.88,1215.27 930.88,1219.68 957.3,1246.1 1001.1,1246.1 1017.3,1262.3 R42.1@1017.3,1286.1
M_COL: J1.34 R15.1 | length 922.7
  Top Layer w8: v1(407.3,1196.1) R15.1@532.3,1196.1
  Bottom Layer w8: J1.34@275.3,501.1 357.3,501.1 407.3,551.1 v1(407.3,1196.1)
M_CRS: J1.36 R16.1 | length 1117
  Top Layer w8: v1(428,1306) 532.2,1306 R16.1@532.3,1306.1
  Bottom Layer w8: J1.36@275.3,401.1 347.3,401.1 428.8,482.6 428.8,1184.37 430.8,1186.37 430.8,1303.2 v1(428,1306)
M_MDC: J1.4 R34.1 | length 704.8
  Bottom Layer w8: J1.4@275.3,2001.1 329.3,2001.1 397.3,1933.1 397.3,1571.1 512.3,1456.1 R34.1@542.3,1456.1
M_MDIO: J1.2 R33.1 | length 752.4
  Bottom Layer w8: J1.2@275.3,2101.1 329.3,2101.1 422.3,2008.1 422.3,1586.1 482.3,1526.1 R33.1@542.3,1526.1
M_RX_CLK: J1.16 R7.1 | length 267.7
  Top Layer w8: J1.16@275.3,1401.1 407.3,1401.1 457.3,1451.1 R7.1@522.3,1451.1
M_RX_DV: J1.14 R6.1 | length 298.5
  Top Layer w8: v1(422.3,1381.1) R6.1@522.3,1381.1
  Bottom Layer w8: J1.14@275.3,1501.1 305.3,1501.1 326.67,1479.73 326.67,1476.73 v1(422.3,1381.1)
M_RX_ER: J1.18 R8.1 | length 277.7
  Top Layer w8: J1.18@275.3,1301.1 357.3,1301.1 407.3,1251.1 R8.1@532.3,1251.1
M_RXD0: J1.12 R5.1 | length 614.4
  Top Layer w8: v1(452.3,1141.1) 452.4,1141 R5.1@533.38,1141
  Bottom Layer w8: J1.12@275.3,1601.1 275.3,1582.7 452.3,1405.7 v1(452.3,1141.1)
M_RXD1: J1.10 R4.1 | length 776.2
  Top Layer w8: v1(472.3,1086.1) R4.1@532.3,1086.1
  Bottom Layer w8: J1.10@275.3,1701.1 305.3,1701.1 337.3,1669.1 337.3,1551.1 474.8,1413.6 474.8,1088.6 v1(472.3,1086.1)
M_RXD2: J1.8 R3.1 | length 918.7
  Top Layer w8: v1(502.3,1026.1) 507.3,1031.1 R3.1@532.3,1031.1
  Bottom Layer w8: J1.8@275.3,1801.1 305.3,1801.1 357.3,1749.1 357.3,1556.1 491.93,1421.47 491.93,1108.86 496,1104.79 496,1032.4 v1(502.3,1026.1)
M_RXD3: J1.6 R2.1 | length 1113.8
  Top Layer w8: v1(502.3,976.1) R2.1@532.3,976.1
  Bottom Layer w8: J1.6@275.3,1901.1 329.3,1901.1 377.3,1853.1 377.3,1561.1 506.93,1431.47 506.93,1115.07 542.3,1079.7 542.3,1016.1 v1(502.3,976.1)
M_TX_CLK: J1.22 R9.1 | length 331.6
  Top Layer w8: J1.22@275.3,1101.1 329.3,1101.1 509.3,921.1 R9.1@532.3,921.1
M_TX_EN: J1.24 R10.1 | length 420.5
  Top Layer w8: J1.24@275.3,1001.1 362.3,1001.1 467.3,896.1 R10.1@652.3,896.1
M_TXD0: J1.26 R11.1 | length 506.5
  Top Layer w8: J1.26@275.3,901.1 387.3,901.1 422.3,866.1 R11.1@767.3,866.1
M_TXD1: J1.28 R12.1 | length 573.9
  Top Layer w8: J1.28@275.3,801.1 347.3,801.1 389.2,843 799.2,843 R12.1@822.3,866.1
M_TXD2: J1.30 R13.1 | length 708.3
  Top Layer w8: J1.30@275.3,701.1 329.3,701.1 377.3,749.1 377.3,791.1 412.3,826.1 860.1,826.1 877.3,843.3 R13.1@877.3,866.1
M_TXD3: J1.32 R14.1 | length 859.2
  Top Layer w8: J1.32@275.3,601.1 347.3,601.1 402.3,656.1 402.3,781.1 427.3,806.1 905.1,806.1 932.3,833.3 R14.1@932.3,866.1
MDC: J15.2 R34.2 U1.25 | length 949.6
  Top Layer w8: U1.25@852.14,1215.27 852.14,1234.12 859.8,1241.78 859.8,1260.42 905.48,1306.1 955.54,1306.1 972.3,1322.86 972.3,1366.1 992.3,1386.1 1077.3,1386.1 J15.2@1117.3,1426.1
  Bottom Layer w8: R34.2@592.3,1456.1 637.3,1411.1 1052.3,1411.1 1067.3,1426.1 J15.2@1117.3,1426.1
MDIO: J15.1 R1.1 R33.2 U1.24 | length 1184.4
  Top Layer w8: U1.24@871.83,1215.27 871.83,1230.63 882.3,1241.1 v1(882.3,1251.1) 917.3,1286.1 958.1,1286.1 992.3,1320.3 992.3,1356.1 1002.3,1366.1 1077.3,1366.1 J15.1@1117.3,1326.1
  Bottom Layer w8: R33.2@592.3,1526.1 687.3,1431.1 1022.3,1431.1 1067.3,1476.1 1147.3,1476.1 1167.3,1456.1 1167.3,1376.1 J15.1@1117.3,1326.1 ; R1.1@877.3,1281.1 877.3,1256.1 v1(882.3,1251.1)
NetJ13_9: J13.9 R38.1 | length 77.8
  Bottom Layer w8: R38.1@1870.92,876.1 1870.92,947.72 J13.9@1875.3,952.1
NetJ13_11: J13.11 R42.2 | length 1121.2
  Top Layer w8: R42.2@1017.3,1331.1 1035.03,1331.1 1085.03,1281.1 1157.1,1281.1 1207.3,1331.3 v1(1207.3,1456.1)
  Mid-Layer 2 w8: v1(1207.3,1456.1) 1452.3,1456.1 1622.3,1286.1 1811.3,1286.1 J13.11@1875.3,1350.1
NetR24_1: R24.1 U1.20 | length 128
  Top Layer w8: U1.20@956.47,1189.68 959.38,1189.68 990.8,1221.1 v1(1007.3,1221.1)
  Bottom Layer w8: v1(1007.3,1221.1) 1017.3,1231.1 R24.1@1017.3,1281.1
PFBOUT: C12.1 C19.2 C22.1 U1.16 U1.19 U1.30 | length 436.8
  Top Layer w8: v1(730,1246) 742.4,1246 753.72,1234.68 U1.30@753.72,1215.27 ; U1.16@956.47,1110.94 973.29,1110.94 977.1,1107.13 1003.33,1107.13 v1(1022.3,1126.1) ; U1.19@956.47,1170 971.2,1170 987.3,1186.1 v1(1022.3,1186.1)
  Bottom Layer w8: 715.28,1288.1 C22.1@737.3,1288.1 ; C22.1@737.3,1266.08 C22.1@737.3,1288.1 ; 737.3,1310.12 C22.1@737.3,1288.1 ; 759.32,1288.1 C22.1@737.3,1288.1 ; C12.1@942.3,1099.1 C12.1@942.3,1121.1 ; C12.1@942.3,1102.6 967.4,1102.6 1002,1068 C19.2@1037,1068 ; C19.2@1012.3,1076.1 1017.3,1071.1 C19.2@1032.3,1071.1
RD+: J13.3 R27.1 U1.12 | length 702.4
  Top Layer w8: U1.12@956.47,1032.2 959.28,1029.39 995.83,1029.39 997.54,1031.1 1099.3,1031.1 1139.4,991 1222.4,991 1237.3,976.1 1457.3,976.1 1477.3,996.1 1477.3,1081.1 J13.3@1432.3,1126.1
RD-: J13.6 R28.1 U1.11 | length 1034
  Top Layer w8: U1.11@956.47,1012.52 1057.88,1012.52 1109.3,961.1 1109.3,959.1 1137,931.4 1447.6,931.4 1502.3,986.1 1502.3,1226.1 1452.3,1276.1 J13.6@1332.3,1276.1
RX_CLK: R7.2 U1.31 | length 337.3
  Top Layer w8: R7.2@572.3,1451.1 625.12,1398.28 625.12,1317.84 677.3,1265.66 677.3,1221.1 708.72,1189.68 U1.31@728.13,1189.68
RX_DV: R6.2 U1.32 | length 293.1
  Top Layer w8: R6.2@572.3,1381.1 610.12,1343.28 610.12,1308.28 657.3,1261.1 657.3,1211.1 698.4,1170 U1.32@728.13,1170
RX_ER: R8.2 R30.2 U1.34 | length 253.7
  Top Layer w8: R8.2@582.3,1251.1 587.3,1251.1 v1(612.3,1226.1) 612.3,1196.1 677.77,1130.63 U1.34@728.13,1130.63
  Bottom Layer w8: R30.2@582.3,1251.1 587.3,1251.1 v1(612.3,1226.1)
RXD0: R5.2 R29.1 U1.36 | length 219
  Top Layer w8: R5.2@580.62,1141 597.4,1141 v1(617.3,1121.1) 647.14,1091.26 U1.36@728.13,1091.26
  Bottom Layer w8: R29.1@580.92,1141.1 607.9,1141.1 617.3,1131.7 v1(617.3,1121.1)
RXD1: R4.2 U1.37 | length 151.8
  Top Layer w8: R4.2@582.3,1086.1 596.83,1071.57 U1.37@728.13,1071.57
RXD2: R3.2 U1.38 | length 154.4
  Top Layer w8: R3.2@582.3,1031.1 603.09,1051.89 U1.38@728.13,1051.89
RXD3: R2.2 U1.39 | length 169.1
  Top Layer w8: R2.2@582.3,976.1 638.4,1032.2 U1.39@728.13,1032.2
TD+: J13.1 R25.1 U1.15 | length 575.7
  Top Layer w8: U1.15@956.47,1091.26 1059.46,1091.26 1109.3,1141.1 1112.3,1141.1 1142.3,1111.1 1277.3,1111.1 1294.2,1128 1360.4,1128 1382.3,1106.1 1382.3,1076.1 J13.1@1432.3,1026.1
TD-: J13.2 R26.1 U1.14 | length 403.6
  Top Layer w8: U1.14@956.47,1071.57 959.29,1074.39 995.83,1074.39 997.12,1073.1 1101.3,1073.1 1109.3,1081.1 1112.3,1081.1 1142.3,1051.1 1307.3,1051.1 J13.2@1332.3,1076.1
